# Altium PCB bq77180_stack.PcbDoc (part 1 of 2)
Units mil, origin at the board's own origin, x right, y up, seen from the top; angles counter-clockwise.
Board outline 2755 x 1574 mil, 2 copper layers (Top Layer, Bottom Layer), stack 30.108 mil thick; 67 components, 47 nets, 175 pads, 125 vias.
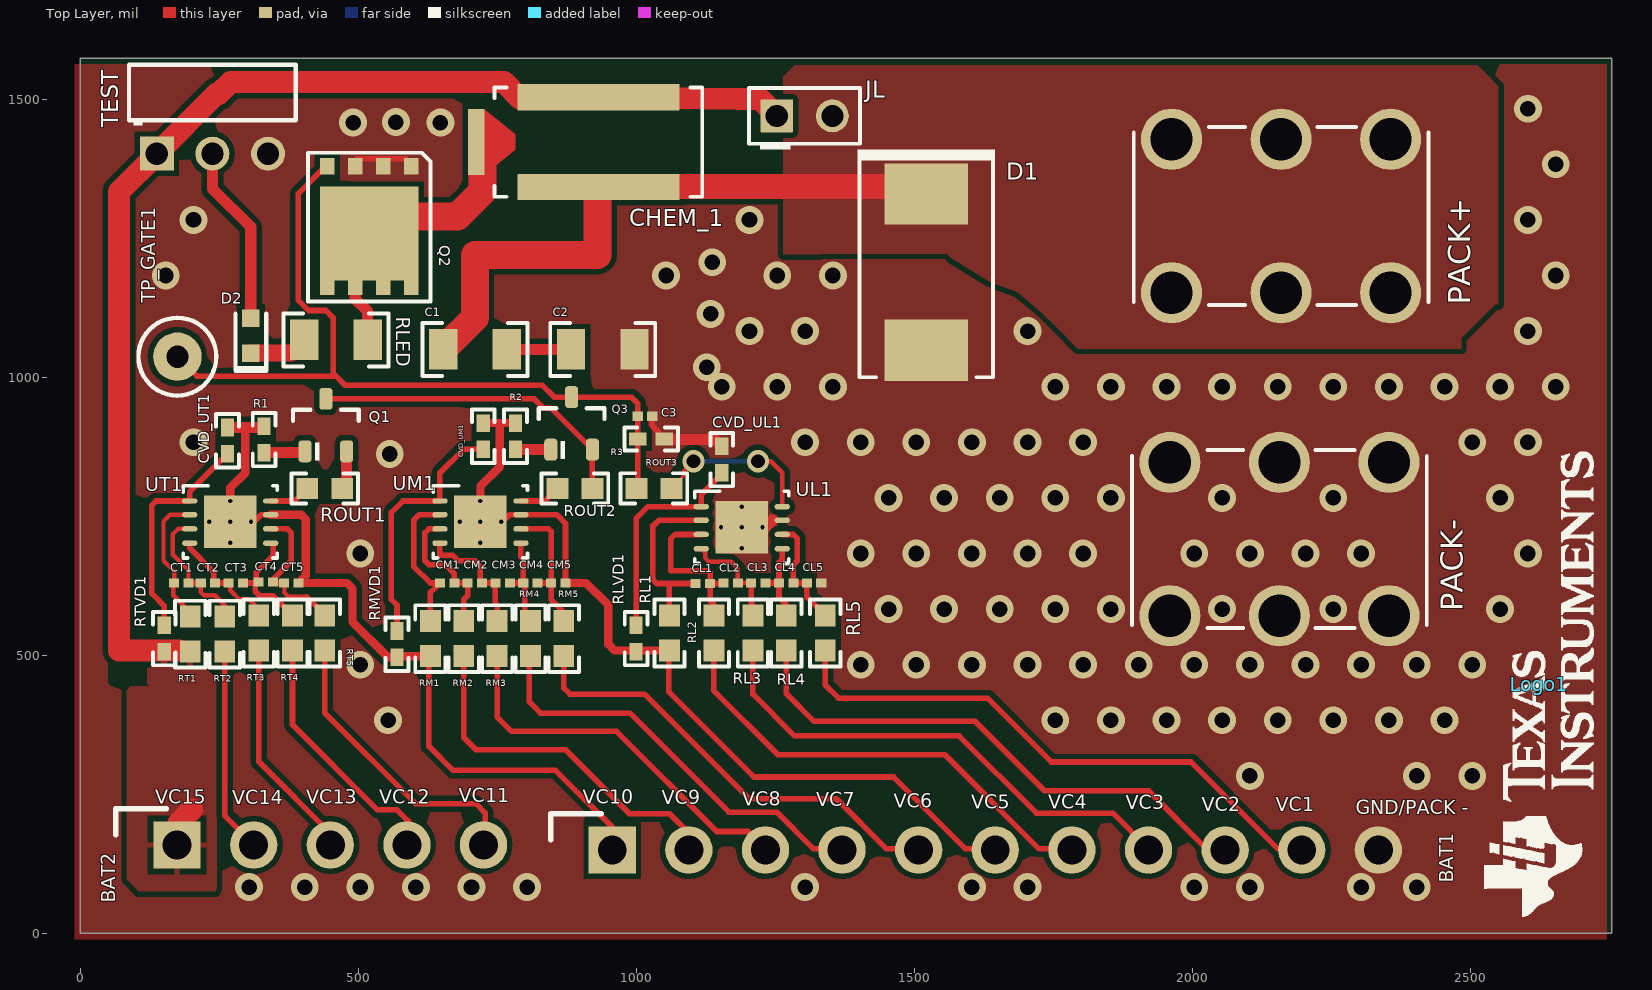
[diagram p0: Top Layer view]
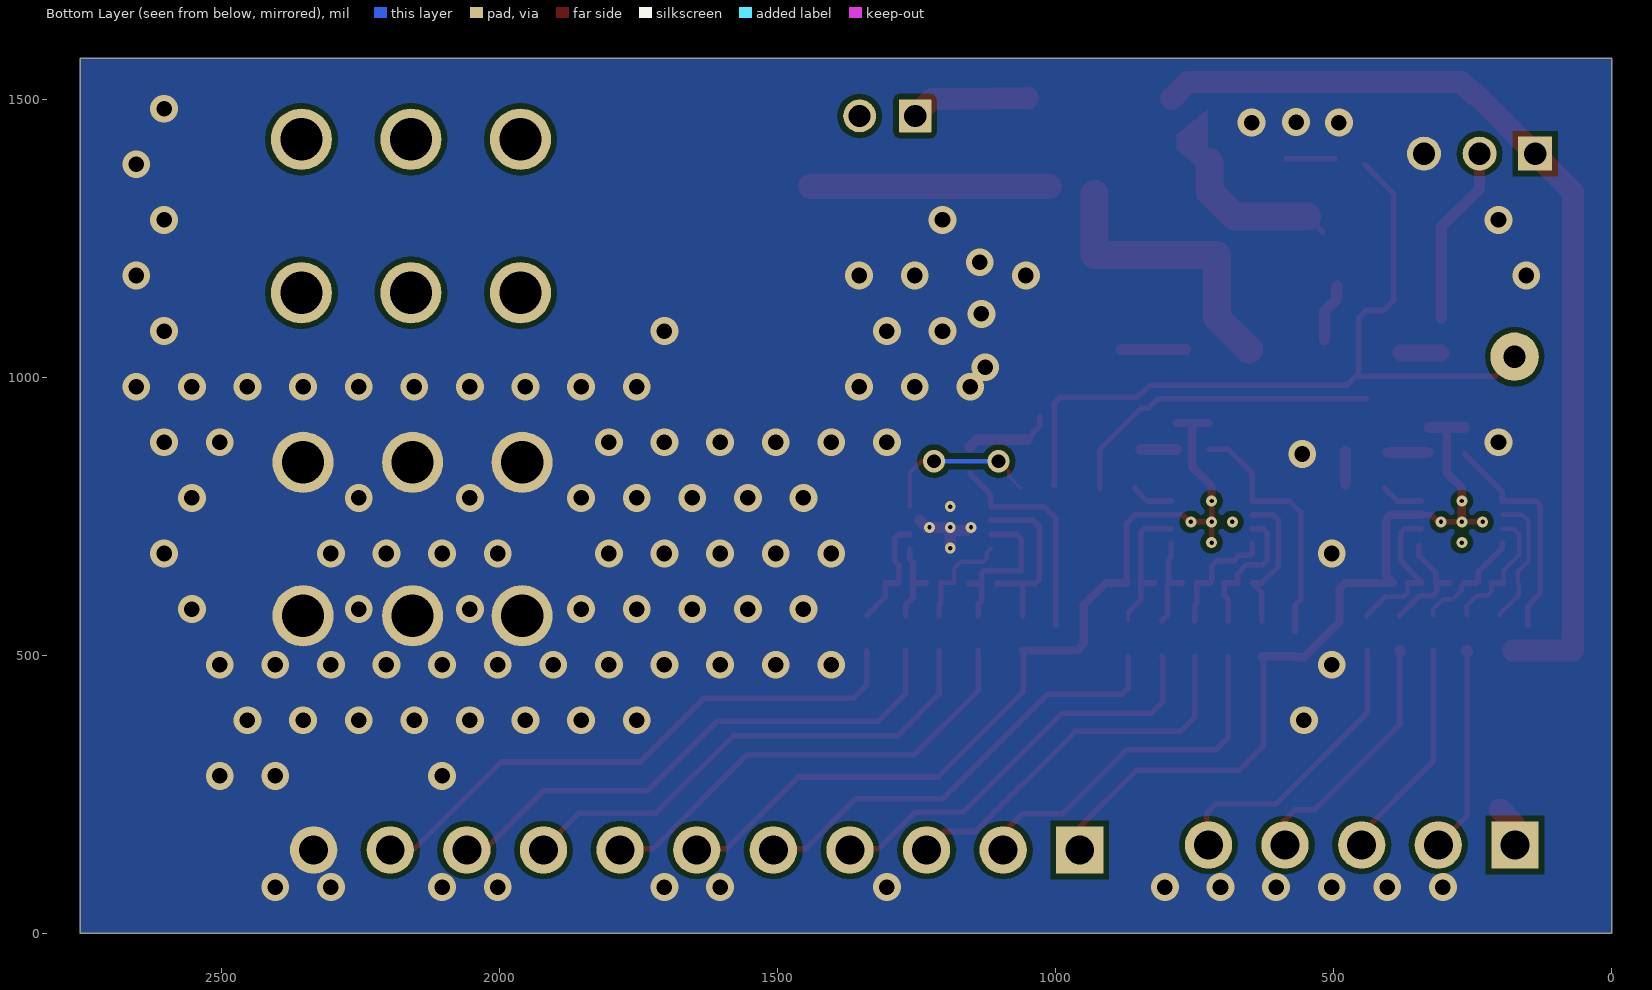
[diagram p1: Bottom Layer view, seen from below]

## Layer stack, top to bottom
Top Solder: solder mask 0.4, Solder Resist, Dk 3.5
Top Layer: signal copper 2.8
Dielectric1: core 24.508, FR-4, Dk 4.8
Bottom Layer: signal copper 2.8
Bottom Solder: solder mask 0.4, Solder Resist, Dk 3.5

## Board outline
0,0 0,1574 2755,1574 2755,0

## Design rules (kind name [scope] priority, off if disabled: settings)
AcuteAngle [All] p1: minimum=4.50000000000000E+0001 checktracksonly=FALSE
AssemblyTestPointUsage [All] p1: valid=2
Clearance Clearance_Keepouts [((IsTrack Or IsArc) And Not InPoly) And IsFree and IsKeepOut vs ((IsTrack Or IsArc) And Not InPoly) And IsFree and IsKeepOut] p1: gap=0
Clearance Clearance_BoardEdge_MountingHoles [OnCopper and InComponentClass('Mounting Holes') vs IsKeepOut] p2: gap=40
Clearance Clearance_BoardEdge_Poly [OnCopper and InPoly vs IsKeepOut] p3: gap=25
Clearance Clearance_BoardEdge [OnCopper and Not InComponentClass('Logo') and not InComponentClass('FiducialMark') and not InRegion(1000,500,4000,800) and Not IsKeepout vs IsKeepOut] p4: gap=75 except(73: Arc-Arc Arc-Track Track-Track)
Clearance Clearance_Poly [InPolygon] p5: gap=10
Clearance [All] p6: gap=7.87 except(7: Arc-Arc Arc-Track Track-Track)
ComponentClearance ComponentClearance_MountingHoles_FiducialMarks [InComponentClass('Mounting Holes') vs InComponentClass('FiducialMark')] p1: gap=50 collisioncheckmode=3 verticalgap=10 showdistances=FALSE
ComponentClearance ComponentClearance_Shunt [InComponentClass('Header') vs InComponentClass('Shunt')] p2: gap=0 collisioncheckmode=3 verticalgap=0 showdistances=FALSE
ComponentClearance ComponentClearance_Logo [InComponentClass('Logo')] p3: gap=50 collisioncheckmode=3 verticalgap=10 showdistances=FALSE
ComponentClearance ComponentClearance_ScrewToNut [(HasFootprint('NY PMS 440 0025 PH')) vs (HasFootprint('Keystone_1902C'))] p4: gap=5 collisioncheckmode=3 verticalgap=10 showdistances=FALSE
ComponentClearance ComponentClearance_MountingHoles [InComponentClass('Mounting Holes')] p5: gap=250 collisioncheckmode=3 verticalgap=100000 showdistances=FALSE
ComponentClearance ComponentClearance_SmallPassives [HasFootprint('0201*') or HasFootprint('0402*') or HasFootprint('0508') or HasFootprint('0603*') or HasFootprint('0612') or HasFootprint('0805*') or HasFootprint('0815*') or HasFootprint('0830*') or HasFootprint('1206*') or HasFootprint('1210*') or HasFootprint('1808*') or HasFootprint('1812*') or HasFootprint('1825*') or HasFootprint('2010*') or HasFootprint('2220*') or HasFootprint('2225*') or HasFootprint('2512*') or HasFootprint('2728*') or HasFootprint('3518*') vs HasFootprint('0201*') or HasFootprint('0402*') or HasFootprint('0508') or HasFootprint('0603*') or HasFootprint('0612') or HasFootprint('0805*') or HasFootprint('0815*') or HasFootprint('0830*') or HasFootprint('1206*') or HasFootprint('1210*') or HasFootprint('1808*') or HasFootprint('1812*') or HasFootprint('1825*') or HasFootprint('2010*') or HasFootprint('2220*') or HasFootprint('2225*') or HasFootprint('2512*') or HasFootprint('2728*') or HasFootprint('3518*')] p6: gap=14.96 collisioncheckmode=3 verticalgap=10 showdistances=FALSE
ComponentClearance ComponentClearance_THtoSMT [IsThruComponent vs IsSMTComponent] p7: gap=40 collisioncheckmode=3 verticalgap=30 showdistances=FALSE
ComponentClearance ComponentClearance_THtoTH [IsThruComponent vs IsThruComponent] p8: gap=30 collisioncheckmode=3 verticalgap=30 showdistances=FALSE
ComponentClearance [All] p9: gap=30 collisioncheckmode=3 verticalgap=10 showdistances=FALSE
DiffPairsRouting [All] p1: maxlimit=100 minlimit=10 mostfreqgap=10 toplayer_minwidth=15 toplayer_maxwidth=15 toplayer_prefwidth=15 bottomlayer_minwidth=15 bottomlayer_maxwidth=15 bottomlayer_prefwidth=15 maxuncoupledlength=1000
FabricationTestPointUsage TestPointUsage [All] p1: valid=2 allowmultiple=FALSE
FabricationTestpoint Testpoint [All] p1: side=3 testpointundercomponent=TRUE minsize=40 maxsize=100 preferedsize=60 minholesize=0 maxholesize=40 preferedholesize=32 testpointgrid=1 allowsidetop=TRUE allowsidebottom=TRUE usegrid=TRUE gridtolerance=0.01
FanoutControl Fanout_LCC [IsLCC] p1: bgadir=Out bgaviamode=Centered fanoutstyle=Auto fanoutdirection=Alternating viagrid=1 // Fanout_LCC (Default Rule)
FanoutControl Fanout_BGA [IsBGA] p2: bgadir=Out bgaviamode=Centered fanoutstyle=Auto fanoutdirection=Alternating viagrid=1 // Fanout_BGA (Default Rule)
FanoutControl Fanout_Default [All] p4: bgadir=Out bgaviamode=Centered fanoutstyle=Auto fanoutdirection=Alternating viagrid=1 // Fanout_Default (Default Rule)
FanoutControl Fanout_Small [(CompPinCount < 5)] p5: bgadir=Out bgaviamode=Centered fanoutstyle=Auto fanoutdirection=OutThenIn viagrid=1 // Fanout_Small (Default Rule)
HoleSize [All] p1: absolutevalues=TRUE maxlimit=251 minlimit=7.87 maxpercent=80.000 minpercent=20.000
HoleToHoleClearance [All] p1: gap=9 allowstackedmicrovias=TRUE
MinimumAnnularRing MinimumAnnularRing_ThermalPadVias [IsVia and InAnyComponent] p1: minimumring=5.91
MinimumAnnularRing [All] p2: minimumring=5
MinimumSolderMaskSliver MinimumSolderMaskSliver_Logo [InComponentClass('Logo') vs InComponentClass('Logo')] p1: minsoldermaskwidth=0.35
MinimumSolderMaskSliver [All] p2: minsoldermaskwidth=2
PlaneConnect [All] p1: planeconnectstyle=Relief reliefexpansion=10 reliefentries=4 reliefconductorwidth=10 reliefairgap=10
PolygonConnect PolygonConnect_8 [All vs IsNamedPolygon('PACK_NEG_L01_P023')] p1: connectstyle=Direct reliefconductorwidth=10 reliefentries=4 polygonreliefangle="90 Angle" airgapwidth=10
PolygonConnect PolygonConnect_7 [All vs IsNamedPolygon('PACK_NEG_L01_P023')] p2: connectstyle=Direct reliefconductorwidth=10 reliefentries=4 polygonreliefangle="90 Angle" airgapwidth=10
PolygonConnect PolygonConnect_6 [All vs IsNamedPolygon('PACK_NEG_L01_P023')] p3: connectstyle=Direct reliefconductorwidth=10 reliefentries=4 polygonreliefangle="90 Angle" airgapwidth=10
PolygonConnect PolygonConnect_5 [All vs IsNamedPolygon('PACK_NEG_L01_P020')] p4: connectstyle=Direct reliefconductorwidth=10 reliefentries=4 polygonreliefangle="90 Angle" airgapwidth=10
PolygonConnect PolygonConnect_4 [All vs IsNamedPolygon('NETC1_1_L01_P021')] p5: connectstyle=Direct reliefconductorwidth=10 reliefentries=4 polygonreliefangle="90 Angle" airgapwidth=10
PolygonConnect PolygonConnect_3 [All vs IsNamedPolygon('NETC1_1_L01_P021')] p6: connectstyle=Direct reliefconductorwidth=10 reliefentries=4 polygonreliefangle="90 Angle" airgapwidth=10
PolygonConnect PolygonConnect_2 [All vs IsNamedPolygon('BottomLayer')] p7: connectstyle=Direct reliefconductorwidth=10 reliefentries=4 polygonreliefangle="90 Angle" airgapwidth=10
PolygonConnect PolygonConnect_1 [All vs IsNamedPolygon('PACK_NEG_L01_P000')] p8: connectstyle=Direct reliefconductorwidth=10 reliefentries=4 polygonreliefangle="90 Angle" airgapwidth=10
PolygonConnect [All] p9: connectstyle=Relief reliefconductorwidth=10 reliefentries=4 polygonreliefangle="90 Angle" airgapwidth=10
RoutingVias ThermalPadVias [IsVia and InAnyComponent] p1: holewidth=7.87 width=19.68 viastyle="Through Hole" minholewidth=7.87 minwidth=19.68 maxholewidth=12.99 maxwidth=23.62
RoutingVias [All] p2: holewidth=16 width=34 viastyle="Through Hole" minholewidth=7.87 minwidth=26 maxholewidth=40 maxwidth=65
SilkToBoardRegionClearance [Not ((IsComment or IsDesignator) And (Hide <> 'False')) and not InRegion(1000,500,4000,800)] p1:
SilkToSilkClearance SilkToSilkClearance_Pb-FreeLogo [(HasFootprint('Pb-Free_Overlay_Medium') OR HasFootprint('Pb-Free_Overlay_Small')) vs (HasFootprint('Pb-Free_Overlay_Medium') OR HasFootprint('Pb-Free_Overlay_Small'))] p1: silktosilkclearance=0
SilkToSilkClearance [All] p2: silktosilkclearance=1
SilkToSolderMaskClearance SilkToComponentPadClearance [IsPad and InAnycomponent] p1: minsilkscreentomaskgap=4 clearancetoexposedcopper=TRUE
SilkToSolderMaskClearance "Silk to Solder Mask Opening" [All] p2: minsilkscreentomaskgap=2 clearancetoexposedcopper=FALSE
SolderMaskExpansion [All] p1: expansion=1.97
Width [All] p1: maxlimit=100 minlimit=6 preferedwidth=10 checkconnectedcopper=TRUE
14 further rules are at their usual default settings.

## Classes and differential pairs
component class Header: JL
component class Logo: Logo1
component class EVM_Hardware: Logo1 ZZ1 ZZ2 ZZ3 ZZ4
component class AssemblyNote: ZZ1 ZZ2 ZZ3 ZZ4
component class bq77180_stack: C1 C2 C3 CHEM_1 CL1 CL2 CL3 CL4 CL5 CM1 CM2 CM3 CM4 CM5 CT1 CT2 CT3 CT4 CT5 CVD_UL1 CVD_UM1 CVD_UT1 D1 D2 JL PACK+ PACK- Q1 Q2 Q3 R1 R2 R3 RL1 RL2 RL3 RL4 RL5 RLED RLVD1 RM1 RM2 RM3 RM4 RM5 RMVD1 ROUT1 ROUT2 ROUT3 RT1 RT2 RT3 RT4 RT5 RTVD1 TEST TP_GATE1 UL1 UM1 UT1

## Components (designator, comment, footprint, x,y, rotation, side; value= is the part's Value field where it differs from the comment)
BAT1 "395021011" HEADER_395021011 1646,12 r0 top
BAT2 "395021005" HEADER_395021005 450,21 r0 top
C1 "12061A222JAT2A" 1206 710,1050 r0 top
C2 "12061A222JAT2A" 1206 940,1050 r0 top
C3 "GRM033R61E104KE14J" 0201_033 1016,930 r0 top
CHEM_1 "SFK-5030" FUSE_SFK-xx30x 932,1423 r0 top
CL1 "GRM033R61E104KE14J" 0201_033 1120,629 r180 top
CL2 "GRM033R61E104KE14J" 0201_033 1170,630 r180 top
CL3 "GRM033R61E104KE14J" 0201_033 1220,630 r180 top
CL4 "GRM033R61E104KE14J" 0201_033 1270,630 r0 top
CL5 "GRM033R61E104KE14J" 0201_033 1320,630 r180 top
CM1 "GRM033R61E104KE14J" 0201_033 660,630 r180 top
CM2 "GRM033R61E104KE14J" 0201_033 710,630 r180 top
CM3 "GRM033R61E104KE14J" 0201_033 760,630 r180 top
CM4 "GRM033R61E104KE14J" 0201_033 810,630 r0 top
CM5 "GRM033R61E104KE14J" 0201_033 860,630 r180 top
CT1 "GRM033R61E104KE14J" 0201_033 182,630 r180 top
CT2 "GRM033R61E104KE14J" 0201_033 230,630 r180 top
CT3 "GRM033R61E104KE14J" 0201_033 280,630 r180 top
CT4 "GRM033R61E104KE14J" 0201_033 334,632 r0 top
CT5 "GRM033R61E104KE14J" 0201_033 380,630 r180 top
CVD_UL1 "C1005X5R1E105K050BC" 0402 1154,852 r90 top
CVD_UM1 "C1005X5R1E105K050BC" 0402 725,894 r90 top
CVD_UT1 "C1005X5R1E105K050BC" 0402 265,886 r90 top
D1 "5.0SMDJ75A" SMC 1522,1189 r270 top
D2 "BR1111C-TR" 1111C_Red 307,1075 r270 top
JL "PEC02SAAN" CONN_PEC02SAAN 1303,1470 r0 top
Logo1 "Texas Instruments" TI_Stacked_Overlay_Small 2624,448 r90 top
PACK+ "8199" SCREW_TERMINAL_8199 2160,1290 r180 top
PACK- "8199" SCREW_TERMINAL_8199 2157,709 r180 top
Q1 "CMPT3906 LEAD FREE" SOT-23 442,914 r90 top
Q2 "CSD18534Q5A" TRANS_NexFET_Q5A 520,1270 r270 top
Q3 "CMPT3906 LEAD FREE" SOT-23 884,917 r90 top
R1 "CRCW040220K0JNED" 0402 331,888 r90 top
R2 "CRCW040220K0JNED" 0402 783,894 r90 top
R3 "CRCW040215K0FKED" 0402 1027,889 r180 top
RL1 "RC0603FR-071KL" 0603 1060,540 r270 top
RL2 "RC0603FR-071KL" 0603 1140,540 r270 top
RL3 "RC0603FR-071KL" 0603 1210,540 r270 top
RL4 "RC0603FR-071KL" 0603 1270,540 r270 top
RL5 "RC0603FR-071KL" 0603 1340,540 r270 top
RLED "CRCW12064K02FKEA" 1206 460,1067 r180 top
RLVD1 "CRCW0402100RFKED" 0402 1000,530 r270 top
RM1 "RC0603FR-071KL" 0603 630,530 r270 top
RM2 "RC0603FR-071KL" 0603 690,530 r270 top
RM3 "RC0603FR-071KL" 0603 750,530 r270 top
RM4 "RC0603FR-071KL" 0603 810,530 r270 top
RM5 "RC0603FR-071KL" 0603 870,530 r270 top
RMVD1 "CRCW0402100RFKED" 0402 570,520 r270 top
ROUT1 "RC0603FR-0721K5L" 0603 440,800 r180 top
ROUT2 "RC0603FR-0710K2L" 0603 890,800 r180 top
ROUT3 "RC0603FR-074K64L" 0603 1032,800 r0 top
RT1 "RC0603FR-071KL" 0603 198,538 r270 top
RT2 "RC0603FR-071KL" 0603 260,538 r270 top
RT3 "RC0603FR-071KL" 0603 321.3,540 r270 top
RT4 "RC0603FR-071KL" 0603 382,540 r270 top
RT5 "RC0603FR-071KL" 0603 440,540 r270 top
RTVD1 "CRCW0402100RFKED" 0402 151.3,530 r270 top
TEST "PBC03SGBN" Sullins_xxC03SGBN 238,1512 r0 top
TP_GATE1 "5005" Keystone5005 175,1037 r90 top
UL1 "BQ771800DPJR" DPJ0008A 1190,730 r0 top
UM1 "BQ771800DPJR" DPJ0008A 720,740 r0 top
UT1 "BQ771800DPJR" DPJ0008A 270,740 r0 top
ZZ1 "This Assembly Note is for PCB labels only" AssemblyNoteLabel 395,2768 r0 top
ZZ2 "These assemblies are ESD sensitive, ESD precautions shall be observed." AssemblyNote 395,2659.11 r0 top
ZZ3 "These assemblies must be clean and free from flux and all contaminants. Use of no clean flux is not acceptable." AssemblyNote 395,2570.56 r0 top
ZZ4 "These assemblies must comply with workmanship standards IPC-A-610 Class 2, unless otherwise specified." AssemblyNote 395,2482 r0 top

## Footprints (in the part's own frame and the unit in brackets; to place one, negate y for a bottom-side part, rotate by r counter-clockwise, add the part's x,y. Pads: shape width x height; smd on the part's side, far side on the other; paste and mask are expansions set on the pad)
0201_033 [mm] "SMD, 2-Leads, Height 0.33mm"
  rect 0.46x0.42 smd mask+0.048: 1(-0.33,0) 2(0.33,0)
  body extent -0.31,-0.16 0.31,0.16, height 0.33
0402 [mm] "0402 from SM-752 data"
  rect 0.8x0.6 smd: 1(-0.6,0) 2(0.6,0)
  silkscreen extent -1.22,-0.52 1.22,0.52, body extent -0.55,-0.3 0.55,0.3, height 0.6
0603 [mm] "0603 from SM-752 data"
  rect 1x0.95 smd: 1(-0.8,0) 2(0.8,0)
  silkscreen extent -1.52,-0.69 1.52,0.69, body extent -0.87,-0.47 0.87,0.47, height 1
1111C_Red [mm] "SMD, 2-Leads, Body 1.6x0.8mm"
  rect 0.8x0.8 smd: 1(-0.8,0) 2(0.8,0)
  silkscreen extent -1,-0.7 1.7,0.7, body extent -0.85,-0.45 0.85,0.45, height 0.8
1206 [mm] "1206 from SM-752 data"
  rect 1.3x1.85 smd: 1(-1.45,0) 2(1.45,0)
  silkscreen extent -2.4,-1.21 2.4,1.21, body extent -1.7,-0.9 1.7,0.9, height 1.35
AssemblyNote [mil] "Assembly Note"
AssemblyNoteLabel [mil] "Assembly Note for PCB Labels"
CONN_PEC02SAAN [mm] "SULLINS"
  rrect7% 1.5x1.5 hole 1.016: 1(-1.27,0)
  round 1.5 hole 1.016: 2(1.27,0)
  silkscreen extent -2.54,-1.52 2.54,1.27, body extent -2.54,-1.27 2.54,1.27, height 8.38
DPJ0008A [mm]
  oval 0.7x0.25 smd: 1(-1.85,0.95) 2(-1.85,0.325) 3(-1.85,-0.325) 4(-1.85,-0.975) 5(1.85,-0.975) 6(1.85,-0.325) 7(1.85,0.325) 8(1.85,0.95)
  rect 2.4x2.4 smd paste-1.2: 9(0,0)
  silkscreen extent -2.15,-1.65 2.15,1.65, body extent -2.05,-1.55 2.05,1.55, height 0.81
FUSE_SFK-xx30x [mm] "Fuse"
  rect 7.4x1.2 smd paste+0 mask+0.07: 1(0,2.05) 3(0,-2.05)
  rect 0.75x3 smd paste+0 mask+0.07: 2(-5.575,0)
  Top Layer region: -5.2,1.5 -5.2,-1.5 -3.8,-0.35 -3.8,0.35
  silkscreen extent -4.75,-2.5 4.75,2.5, body extent -4.75,-2.5 4.75,2.5, height 2
HEADER_395021005 [mil] "MOLEX"
  rect 85x85 hole 52: 1(-275.59,137.8)
  round 85 hole 52: 2(-137.8,137.8) 3(0,137.8) 4(137.8,137.8) 5(275.59,137.8)
  silkscreen extent -453,-184 386,203, body extent -371,-172 373,188, height 277
HEADER_395021011 [mil] "MOLEX"
  rect 85x85 hole 52: 1(-688.98,137.8)
  round 85 hole 52: 2(-551.18,137.8) 3(-413.39,137.8) 4(-275.59,137.8) 5(-137.8,137.8) 6(0,137.8) 7(137.8,137.8) 8(275.59,137.8) 9(413.39,137.8) 10(551.18,137.8) 11(688.98,137.8)
  silkscreen extent -866,-184 799,203, body extent -783,-172 788,188, height 270
Keystone5005 [mil] "Keystone Compact loops"
  round 87 hole 40: 1(0,0)
  silkscreen extent -70,-70 70,70, body extent -63,-63 62,63, height 225
SCREW_TERMINAL_8199 [mil] "Keystone Teminal, 30 Amp"
  round 110 hole 76: 1(-197,138) 2(0,138) 3(197,138) 4(197,-138) 5(0,-138) 6(-197,-138)
  silkscreen extent -265,-160 265,160, body extent -253,-177 254,177, height 325
SMC [mil] "Molded Diode, 2-Leads, Body 6.9x5.8mm, IPC Medium Density, based on OnSemi component dimensions and land patterns"
  rect 110x150 smd: 1(-140.49,0) 2(140.49,0)
  silkscreen extent -221,-124 189,123, body extent -156,-116 156,116, height 91
SOT-23 [mm] "SOT23, 3-Leads, Body 2.9x1.3mm, Pitch 0.95mm, Lead Span 2.5mm, IPC Medium Density"
  rrect50% 1x0.6 smd: 1(-1.2,0.95) 2(-1.2,-0.95) 3(1.2,0)
  silkscreen extent -1.63,-1.5 0.7,1.5, body extent -1.16,-1.45 1.21,1.45, height 1
Sullins_xxC03SGBN [mm] "Header, 2.54 mm, 3x1, R/A, TH"
  rect 1.55x1.55 hole 1.02: 1(-2.54,-2.79)
  round 1.55 hole 1.02: 2(0,-2.79) 3(2.54,-2.79)
  silkscreen extent -3.81,-1.5 3.81,1.27, body extent -3.81,-3.11 3.81,9.35, height 3.69
TI_Stacked_Overlay_Small [mil]
  silkscreen extent -418,-98 418,98
TRANS_NexFET_Q5A [mm] "TI recommended land pattern (nominal) M0139-01"
  rect 0.75x0.675 smd paste-0.1 mask+0.051: 1(-2.776,1.917) 2(-2.776,0.639) 3(-2.776,-0.639) 4(-2.776,-1.917)
  rect 0.655x0.675 smd paste-0.1 mask+0.051: 5(2.776,-1.917) 6(2.776,-0.639) 7(2.776,0.639) 8(2.776,1.917)
  rect 4.295x4.51 smd paste-2.2 mask+0.051: 9(0.301,0)
  silkscreen extent -3.4,-2.8 3.4,2.8, body extent -3.05,-2.5 3.05,2.5, height 1.11

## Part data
BAT1: "Terminal block, 3.5mm, 11x1, R/A, TH"
BAT2: "Header (shrouded), 3.5mm, 5x1, R/A, TH"
C1 C2: "CAP, CERM, 2200 pF, 100 V, +/- 5%, C0G/NP0, 1206"
C3 CL1 CL2 CL3 CL4 CL5 CM1 CM2 CM3 CM4 CM5 CT1 CT2 CT3 CT4 CT5: "CAP, CERM, 0.1 µF, 25 V, +/- 10%, X5R, 0201"
CHEM_1: "Fuse, 30 A, 62 VDC, SMD"
CVD_UL1 CVD_UM1 CVD_UT1: "CAP, CERM, 1 µF, 25 V, +/- 10%, X5R, 0402"
D1: "Diode, TVS, Uni, 75 V, 5000 W, SMC"
D2: "LED, Red, SMD"
JL: "Header, 100mil, 2x1, Tin, TH"
Logo1: library part TI_Logo, "Texas Instrument Corporate Signature"
PACK+ PACK-: "TERMINAL SCREW PC 30AMP, TH"
Q1 Q3: library part "CMPT3906 LEAD FREE, Central Semiconductor", "Transistor, PNP, 40 V, 0.2 A, SOT-23"
Q2: "MOSFET, N-CH, 60 V, 50 A, SON 5x6mm"
R1 R2: "RES, 20 k, 5%, 0.063 W, 0402"
R3: "RES, 15.0 k, 1%, 0.063 W, 0402"
RL1 RL2 RL3 RL4 RL5 RM1 RM2 RM3 RM4 RM5 RT1 RT2 RT3 RT4 RT5: "RES, 1.00 k, 1%, 0.1 W, 0603"
RLED: "RES, 4.02 k, 1%, 0.25 W, 1206"
RLVD1 RMVD1 RTVD1: "RES, 100, 1%, 0.063 W, 0402"
ROUT1: "RES, 21.5 k, 1%, 0.1 W, 0603"
ROUT2: "RES, 10.2 k, 1%, 0.1 W, 0603"
ROUT3: "RES, 4.64 k, 1%, 0.1 W, 0603"
TEST: "Header, 2.54 mm, 3x1, Gold, R/A, TH"
TP_GATE1: "Test Point, Compact, Red, TH"
UL1 UM1 UT1: "Overvoltage Protection for 2-Series to 5-Series Cell Li-Ion Batteries with Internal Delay Timer, DPJ0008A"
ZZ1: library part AssemblyNoteLabel
ZZ2 ZZ3 ZZ4: library part AssemblyNote

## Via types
v1: diameter 50, hole 28, Top Layer to Bottom Layer, 108 vias
v2: diameter 19.68, hole 7.87, Top Layer to Bottom Layer, 15 vias
v3: diameter 40, hole 25, Top Layer to Bottom Layer, 2 vias

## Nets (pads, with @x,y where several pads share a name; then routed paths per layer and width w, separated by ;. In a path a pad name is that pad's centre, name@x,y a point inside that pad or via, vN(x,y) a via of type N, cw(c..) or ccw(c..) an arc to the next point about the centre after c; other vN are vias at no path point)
NetC1_1: C1.1 CHEM_1.3 D1.1 JL.2 PACK+.1 PACK+.2 PACK+.3 PACK+.4 PACK+.5 PACK+.6 | length 954.1
  Top Layer w45: CHEM_1.3@1011.71,1343 1441.49,1343
  Top Layer w50: C1.1@652.91,1050 710,1107.09 710,1220 930.71,1220 CHEM_1.3@930.71,1330
NetC1_2: C1.2 C2.1 | length 115.8
  Top Layer w20: C1.2@767.09,1050 C2.1@882.91,1050
NetC3_1: C3.1 Q2.4 Q3.3 R3.2 ROUT3.1 TP_GATE1.1 | length 1458.3
  Top Layer w10: TP_GATE1.1@175,1037 210,1002 460,1002 ; Q2.4@444.51,1382.3 392,1329.8 392,1139 411,1120 442,1120 455,1107 455,1007 460,1002 ; 985.24,964 992,964 1003.01,952.99 C3.1@1003.01,930 1003.01,806.5 ROUT3.1@1003.5,806 ; 985.24,964.24 Q3.3@884,964.24 852.76,964.24 831,986 476,986 460,1002
NetCHEM_1_2: CHEM_1.2 Q2.5 Q2.6 Q2.7 Q2.8 Q2.9 RLED.1 | length 393.1
  Top Layer w10: Q2.9@520,1261.14 Q2.9@547.86,1289
  Top Layer w20: Q2.6@494.84,1163.7 494.84,1141.16 517.09,1118.91 RLED.1@517.09,1067
  Top Layer w50: Q2.9@547.86,1289 679,1289 724,1334 CHEM_1.2@724,1387
NetCL1_1: CL1.1 CL2.2 RL2.1 UL1.3 | length 291.1
  Top Layer w10: UL1.3@1117.17,717.2 1070.2,717.2 1062,709 1062,652 1129,652 1132.99,648.01 CL1.1@1132.99,630 ; RL2.1@1140,571.5 1140,591.02 1132.99,598.03 CL1.1@1132.99,629 1156.01,629 CL2.2@1157.01,630
NetCL1_2: CL1.2 RL1.1 UL1.2 | length 322.6
  Top Layer w10: 1036,630 1030,636 1030,732 1040.8,742.8 UL1.2@1117.17,742.8 ; 1037,629 CL1.2@1107.01,629 ; RL1.1@1060,571.5 1060,628
NetCL2_1: CL2.1 CL3.2 RL3.1 UL1.4 | length 196.1
  Top Layer w8: UL1.4@1117.17,691.61 1124.02,684.76 1124.02,674.98 1131,668 1171,668 1182.99,656.01 CL2.1@1182.99,630 CL3.2@1207.01,630
  Top Layer w10: CL3.2@1207.01,630 1207.01,592.99 1210,590 RL3.1@1210,571.5
NetCL3_1: CL3.1 CL4.1 RL4.1 UL1.5 | length 151.9
  Top Layer w10: CL3.1@1232.99,630 CL4.1@1257.01,630 ; UL1.5@1262.83,691.61 1262.83,672.83 1257.01,667.01 CL4.1@1257.01,630 ; RL4.1@1270,571.5 1270,591.02 1257.01,604.02 CL4.1@1257.01,630
NetCL4_2: CL4.2 CL5.2 RL5.1 UL1.6 | length 209.2
  Top Layer w10: UL1.6@1262.83,717.2 1282.8,717.2 1290,710 1290,670 1282.99,662.99 CL4.2@1282.99,630 CL5.2@1307.01,630 1307.01,604.49 RL5.1@1340,571.5
NetCM1_1: CM1.1 CM2.2 RM2.1 UM1.3 | length 255.1
  Top Layer w10: UM1.3@647.17,727.2 627.2,727.2 620,720 620,670 627.01,662.99 657.01,662.99 672.99,647.01 CM1.1@672.99,630 CM2.2@697.01,630 697.01,607.01 690,600 RM2.1@690,561.5
NetCM1_2: CM1.2 RM1.1 UM1.2 | length 269.1
  Top Layer w10: RM1.1@630,561.5 630,612.99 CM1.2@647.01,630 630,630 600,660 600,742.8 610,752.8 UM1.2@647.17,752.8
NetCM2_1: CM2.1 CM3.2 RM3.1 UM1.4 | length 226.1
  Top Layer w10: UM1.4@647.17,701.61 647.17,682.83 650,680 670,680 680,670 710,670 720,660 720,632.99 CM2.1@722.99,630 CM3.2@747.01,630 747.01,592.99 750,590 RM3.1@750,561.5
NetCM3_1: CM3.1 CM4.1 RM4.1 UM1.5 | length 171.2
  Top Layer w10: CM3.1@772.99,630 CM4.1@797.01,630 ; UM1.5@792.83,701.61 792.83,677.17 797.01,672.99 CM4.1@797.01,630 ; RM4.1@810,561.5 800,571.5 800,627.01 CM4.1@797.01,630
NetCM4_2: CM4.2 CM5.2 RM5.1 UM1.6 | length 251
  Top Layer w6: RM5.1@870,561.5 RM5.1@870,577
  Top Layer w10: UM1.6@792.83,727.2 842.8,727.2 847.01,722.99 CM5.2@847.01,630 ; CM4.2@822.99,630 CM5.2@847.01,630 ; RM5.1@870,577 847.01,599.99 CM5.2@847.01,630
NetCT1_1: CT1.1 CT2.2 RT2.1 UT1.3 | length 243.6
  Top Layer w8: CT1.1@194.99,630 194.99,653.01 167,681 167,718 176.2,727.2 UT1.3@197.17,727.2 ; CT2.2@217.01,630 217.01,613.86 222.87,608 242,608 261.3,588.7 RT2.1@261.3,571.5
  Top Layer w10: CT1.1@194.99,630 CT2.2@217.01,630
NetCT1_2: CT1.2 RT1.1 UT1.2 | length 242.9
  Top Layer w8: 150,740 150,670 169.01,650.99 CT1.2@169.01,630 167.73,628.72 167.73,608 201.3,574.43 RT1.1@201.3,571.5 ; 150,741 161.8,752.8 UT1.2@197.17,752.8
NetCT2_1: CT2.1 CT3.2 RT3.1 UT1.4 | length 205.8
  Top Layer w8: CT3.2@267.01,630 270,627.01 270,617 285.98,601.02 303.43,601.02 321.3,583.15 RT3.1@321.3,571.5
  Top Layer w10: UT1.4@197.17,701.61 197.17,692.83 240,650 240,632.99 CT2.1@242.99,630 CT3.2@267.01,630
NetCT3_1: CT3.1 CT4.1 RT4.1 UT1.5 | length 200.4
  Top Layer w10: CT3.1@292.99,630 315,630 315,615 323,607 345,607 ; CT4.1@317.01,630 317.01,649.01 347,679 UT1.5@347,697.45 ; 346.5,607 RT4.1@382,571.5
NetCT4_2: CT4.2 CT5.2 RT5.1 UT1.6 | length 278
  Top Layer w8: 367.01,612.99 375,605 407.8,605 ; 367.62,612.99 CT5.2@367.62,630
  Top Layer w10: UT1.6@342.83,727.2 372.8,727.2 380,720 380,670 342.99,632.99 342.99,630 CT5.2@367.01,630 ; 407.8,605 RT5.1@441.3,571.5
NetCVD_UL1_1: CVD_UL1.1 RLVD1.1 UL1.1 | length 394.6
  Top Layer w10: RLVD1.1@1000,553.62 1000,746 1021.4,767.4 UL1.1@1117.17,767.4 1117.17,789.17 1154,826 CVD_UL1.1@1154,828.38
NetCVD_UM1_1: CVD_UM1.1 RMVD1.1 UM1.1 | length 459.2
  Top Layer w10: RMVD1.1@570,543.62 570,590 560,600 560,757 580.4,777.4 UM1.1@647.17,777.4 647.17,828.17 689.38,870.38 CVD_UM1.1@725,870.38
NetCVD_UT1_1: CVD_UT1.1 RTVD1.1 UT1.1 | length 409.9
  Top Layer w10: RTVD1.1@151.3,553.62 151.3,588.7 129,611 129,770 136.4,777.4 UT1.1@197.17,777.4 197.17,794.54 CVD_UT1.1@265,862.38
NetD2_1: D2.1 TEST.2 | length 324.2
  Top Layer w20: TEST.2@238,1402.16 238,1339 307,1270 D2.1@307,1106.5
NetD2_2: D2.2 RLED.2 | length 72.4
  Top Layer w30: D2.2@307,1043.5 RLED.2@379.42,1043.5
NetQ1_1: Q1.1 R1.1 | length 71.2
  Top Layer w20: R1.1@331,864.38 Q1.1@402.22,864.38
NetQ1_2: Q1.2 ROUT1.1 | length 58.9
  Top Layer w20: ROUT1.1@479.4,807.91 Q1.2@479.4,866.76
NetQ1_3: Q1.3 Q3.2 ROUT2.1 | length 587.1
  Top Layer w10: Q1.3@442,961.24 816.76,961.24 833.44,944.56 846.6,944.56 Q3.2@921.4,869.76 921.5,869.66 ROUT2.1@921.5,800
NetQ3_1: Q3.1 R2.1 | length 63
  Top Layer w20: R2.1@783.62,869.76 Q3.1@846.6,869.76
NetROUT1_2: ROUT1.2 UT1.8 | length 75
  Top Layer w10: UT1.8@342.83,777.4 385.91,777.4 ROUT1.2@408.5,800
NetROUT2_2: ROUT2.2 UM1.8 | length 75
  Top Layer w10: UM1.8@792.83,777.4 835.91,777.4 ROUT2.2@858.5,800
NetROUT3_2: ROUT3.2 UL1.8 | length 306.2
  Top Layer w6: ROUT3.2@1063.5,800 1085,821.5 1085,831 v3(1103,849) v3@1103,856.75 ; v3@1095,846.13 v3@1095,850
  Top Layer w8: v3(1219,849) 1242,849 1262.83,828.17 UL1.8@1262.83,767.4
  Bottom Layer w8: v3(1103,849) v3(1219,849)
"PACK NEG": BAT1.11 C2.2 C3.2 CL5.1 CVD_UL1.2 D1.2 PACK-.1 PACK-.2 PACK-.3 PACK-.4 PACK-.5 PACK-.6 Q2.1 Q2.2 Q2.3 R3.1 TEST.3 UL1.7 UL1.9 | length 287.2
  Top Layer w10: C3.2@1028.99,930 1028.99,912.56 1040.76,900.79 1040.76,898.86 R3.1@1051.62,888
  Top Layer w20: v1@568,1454.75 v1(568,1459) ; R3.1@1051.62,888 1141.62,888 CVD_UL1.2@1154,875.62 ; UL1.9@1158,724.6 UL1.9@1190,724.6 ; UL1.9@1190,698 UL1.9@1190,724.6 ; 1244.8,742.8 1232,730 v2(1227.4,730) v2(1190,730) UL1.9@1190,724.6
  other v1: 304,83 404,83 504,83 604,83 704,83 804,83 1304,83 1604,83 1704,83 2004,83 2104,83 2304,83 2404,83 2104,283 2404,283 2504,283 554,383 1754,383 1854,383 1954,383 2054,383 2154,383 2254,383 2354,383 2454,383 504,483 1404,483 1504,483 1604,483 1704,483 1804,483 1904,483 2004,483 2104,483 2204,483 2304,483 2404,483 2504,483 1454,583 1554,583 1654,583 1754,583 1854,583 2054,583 2254,583 2554,583 504,683 1404,683 1504,683 1604,683 1704,683 1804,683 2004,683 2104,683 2204,683 2304,683 2604,683 1454,783 1554,783 1654,783 1754,783 1854,783 2054,783 2254,783 2554,783 557,862 204,883 1304,883 1404,883 1504,883 1604,883 1704,883 1804,883 2504,883 2604,883 1154,983 1254,983 1354,983 1754,983 1854,983 1954,983 2054,983 2154,983 2254,983 2354,983 2454,983 2554,983 2654,983 1127,1018 1204,1083 1304,1083 1704,1083 2604,1083 1134,1114 154,1183 1054,1183 1254,1183 1354,1183 2654,1183 1137,1207 204,1283 1204,1283 2604,1283 2654,1383 491,1458 648,1458 2604,1483
  other v2: 1190,692.6 1152.6,730 1190,767.4
VC1: BAT1.10 RL5.2 | length 1041
  Top Layer w10: RL5.2@1340,508.5 1340,447 1364,423 1632,423 1747,308 1998,308 2154.2,151.8 BAT1.10@2197.18,151.8
VC2: BAT1.9 RL4.2 | length 982.5
  Top Layer w10: RL4.2@1270,508.5 1270,431 1320,381 1610,381 1735,256 1922,256 2026.2,151.8 BAT1.9@2059.39,151.8
VC3: BAT1.8 RL3.2 | length 905.3
  Top Layer w10: RL3.2@1210,508.5 1210,430 1285,355 1581,355 1720,216 1857.39,216 BAT1.8@1921.59,151.8
VC4: BAT1.7 RL2.2 | length 834
  Top Layer w10: RL2.2@1140,508.5 1140,436 1255,321 1555.59,321 1724.8,151.8 BAT1.7@1783.8,151.8
VC5: BAT1.6 CM5.1 CVD_UM1.2 R2.2 RL1.2 RLVD1.2 UM1.7 UM1.9 | length 1615.1
  Top Layer w10: v2(720,702.6) v2(720,740) ; v2(720,777.4) v2(720,740) ; CM5.1@872.99,630 872.99,737.01 857.2,752.8 UM1.7@792.83,752.8 772.8,752.8 760,740 v2(757.4,740) v2(720,740) ; RL1.2@1059,507.5 1059,434 1212,281 1463,281 1592.2,151.8 BAT1.6@1646,151.8
  Top Layer w15: v2(720,777.4) 720,804 755,839 755,917.62 ; CVD_UM1.2@725,917.62 755,917.62 ; R2.2@783,917.62 755,917.62 ; CM5.1@872.99,630 910,630 950,590 950,520 961.5,508.5 RL1.2@1060,508.5
  other v2: 682.6,740
VC6: BAT1.5 RM5.2 | length 815.5
  Top Layer w10: RM5.2@870,498.5 870,441 881,430 1015,430 1203,242 1360,242 1450.2,151.8 BAT1.5@1508.2,151.8
VC7: BAT1.4 RM4.2 | length 755.2
  Top Layer w10: RM4.2@810,498.5 808,496.5 808,416 828,396 989,396 1167,218 1253,218 1319.2,151.8 BAT1.4@1370.41,151.8
VC8: BAT1.3 RM3.2 | length 690.4
  Top Layer w10: RM3.2@750,498.5 750,389 776,363 965,363 1145,183 1201.41,183 BAT1.3@1232.61,151.8
VC9: BAT1.2 RM2.2 | length 650.9
  Top Layer w10: RM2.2@690,498.5 690,352 712,330 873,330 988,215 1060,215 1094.82,180.18 BAT1.2@1094.82,151.8
VC10: BAT1.1 CT5.1 CVD_UT1.2 R1.2 RM1.2 RMVD1.2 UT1.7 UT1.9 | length 1460.1
  Top Layer w10: v2(232.6,740) v2(270,740) v2(307.4,740) 313,740 325.8,752.8 UT1.7@342.83,752.8 ; RM1.2@627,495.5 627,337 671,293 855,293 957.02,190.98 BAT1.1@957.02,151.8
  Top Layer w15: v2(270,740) v2(270,777.4) 270,801 297,828 297,909.62 ; UT1.7@342.83,752.8 397.2,752.8 405.98,744.02 405.98,642.99 CT5.1@392.99,630 480,630 490,620 490,560 553.62,496.38 RMVD1.2@570,496.38 ; RMVD1.2@572.13,498.5 RM1.2@630,498.5
  Top Layer w20: CVD_UT1.2@265,909.62 297,909.62 R1.2@329,909.62
  other v2: 270,702.6
VC11: BAT2.5 RT5.2 | length 535.1
  Top Layer w10: RT5.2@440,508.5 440,396 603,233 712,233 728.59,216.41 BAT2.5@728.59,156.8
VC12: BAT2.4 RT4.2 | length 460.5
  Top Layer w10: RT4.2@382,508.5 382,375 535,222 570,222 590.8,201.2 BAT2.4@590.8,156.8
  Top Layer w20: RT4.2@380,507.2 RT4.2@381.3,508.5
